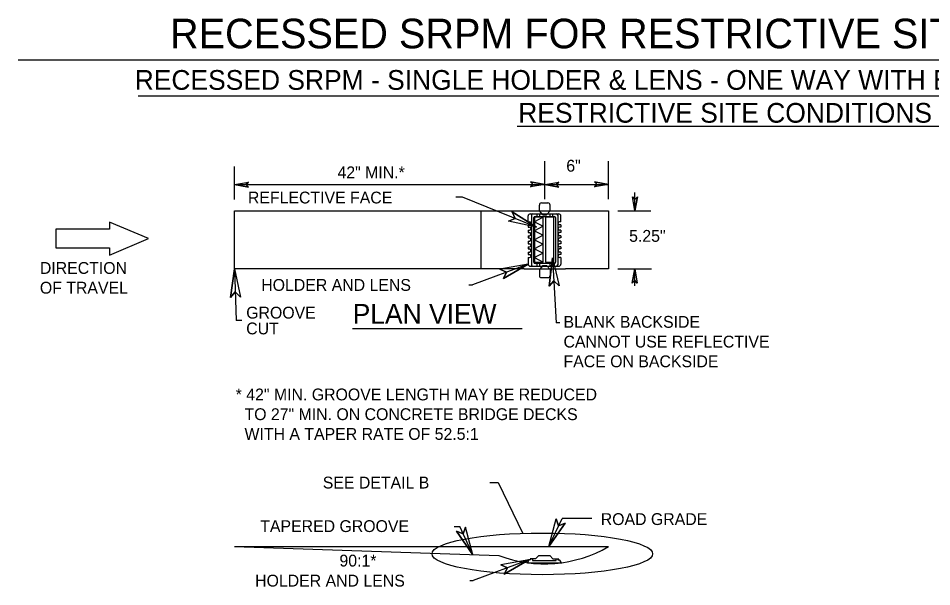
# Model space of a CAD drawing. Extents: x 12.2 to 19.6, y 5.9 to 16.3.
# Drawn here: x 12.247 to 16.872, y 13.404 to 16.284 of the extents above; entities that cross this region are included whole.
import ezdxf

# ---------------------------------------------------------------- set-up
doc = ezdxf.new("R2010")
doc.units = 0
for name, color, linetype in [('C-TRAF-FLOW', 7, 'Continuous'), ('DETL-DIMS', 7, 'Continuous'), ('DETL-LINE', 7, 'Continuous'), ('DETL-NOTE', 7, 'Continuous'), ('DETL-TITL', 7, 'Continuous')]:
    doc.layers.add(name, color=color, linetype=linetype)

msp = doc.modelspace()

# ---------------------------------------------------------------- linework, layer by layer
at = {"layer": 'C-TRAF-FLOW'}
msp.add_lwpolyline([(12.9062, 15.1683), (12.7089, 15.2519), (12.7089, 15.2152), (12.4365, 15.2152), (12.4365, 15.1214), (12.7089, 15.1214), (12.7089, 15.0847)], close=True, dxfattribs=at)
at = {"layer": 'DETL-DIMS'}
for p, q in [((14.9122, 15.3677), (14.9122, 15.5608)), ((15.2357, 15.3677), (15.2357, 15.5608)), ((13.3409, 15.3665), (13.3409, 15.5335)), ((13.3409, 15.442), (13.4125, 15.4541)), ((13.3989, 15.4416), (13.4125, 15.4541)), ((14.9122, 15.442), (14.8408, 15.4551)), ((14.8408, 15.4551), (14.8542, 15.4424)), ((14.9122, 15.442), (14.9838, 15.4541)), ((14.9702, 15.4416), (14.9838, 15.4541)), ((15.2357, 15.442), (15.1643, 15.4551)), ((15.1643, 15.4551), (15.1777, 15.4424)), ((13.3409, 15.442), (13.4123, 15.4289)), ((13.3409, 15.442), (14.9122, 15.442)), ((13.4123, 15.4289), (13.3989, 15.4416)), ((14.8542, 15.4424), (14.8406, 15.4299)), ((14.9122, 15.442), (14.8406, 15.4299)), ((14.9122, 15.442), (14.9836, 15.4289)), ((14.9122, 15.442), (15.2357, 15.442)), ((14.9836, 15.4289), (14.9702, 15.4416)), ((15.1777, 15.4424), (15.1641, 15.4299)), ((15.2357, 15.442), (15.1641, 15.4299)), ((14.4965, 15.3784), (14.4614, 15.3784)), ((14.8707, 15.2262), (14.4965, 15.3784)), ((15.3687, 15.3082), (15.3566, 15.3798)), ((15.3691, 15.3662), (15.3566, 15.3798)), ((15.3687, 15.3082), (15.3687, 15.4014)), ((15.3687, 15.3082), (15.3818, 15.3796)), ((15.3818, 15.3796), (15.3691, 15.3662)), ((14.7632, 15.27), (14.7288, 15.2568)), ((14.8707, 15.2262), (14.7478, 15.3034)), ((14.7478, 15.3034), (14.7632, 15.27)), ((15.2828, 15.3082), (15.4498, 15.3082)), ((14.8707, 15.2262), (14.7288, 15.2568)), ((14.8283, 15.0385), (14.5462, 14.9342)), ((14.8283, 15.0385), (14.6854, 15.0125)), ((14.8283, 15.0385), (14.7029, 14.9653)), ((14.9508, 15.0705), (14.9343, 14.9262)), ((14.9508, 15.0705), (14.9846, 14.9292)), ((14.9508, 15.0705), (14.9707, 14.741)), ((13.3409, 15.014), (13.3209, 14.8703)), ((13.3409, 15.014), (13.3503, 14.7528)), ((13.3409, 15.014), (13.3712, 14.872)), ((14.7195, 14.9983), (14.6854, 15.0125)), ((14.7029, 14.9653), (14.7195, 14.9983)), ((15.2828, 15.014), (15.4532, 15.014)), ((15.3687, 15.014), (15.3556, 14.9426)), ((15.3687, 15.014), (15.3808, 14.9424)), ((15.3687, 14.928), (15.3687, 15.014)), ((14.9343, 14.9262), (14.9578, 14.9546)), ((14.9578, 14.9546), (14.9846, 14.9292)), ((15.3556, 14.9426), (15.3683, 14.956)), ((15.3683, 14.956), (15.3808, 14.9424)), ((13.3209, 14.8703), (13.345, 14.8981)), ((13.345, 14.8981), (13.3712, 14.872)), ((14.5287, 14.9342), (14.5462, 14.9342)), ((13.3787, 14.7528), (13.3503, 14.7528)), ((14.9883, 14.741), (14.9707, 14.741)), ((14.9334, 13.6074), (14.9999, 13.7506)), ((14.9334, 13.6074), (14.9708, 13.7477)), ((14.9823, 13.7127), (14.9708, 13.7477)), ((15.1507, 13.7506), (14.9999, 13.7506)), ((14.4537, 13.7095), (14.4821, 13.7095)), ((14.5486, 13.5663), (14.4821, 13.7095)), ((14.4997, 13.6715), (14.5112, 13.7066)), ((14.5486, 13.5663), (14.5112, 13.7066)), ((14.9334, 13.6074), (15.0165, 13.7265)), ((15.0165, 13.7265), (14.9823, 13.7127)), ((14.5486, 13.5663), (14.4655, 13.6853)), ((14.4655, 13.6853), (14.4997, 13.6715)), ((14.8321, 13.5405), (14.55, 13.4362)), ((14.8321, 13.5405), (14.6892, 13.5145)), ((14.7232, 13.5003), (14.6892, 13.5145)), ((14.8321, 13.5405), (14.7067, 13.4673)), ((14.7067, 13.4673), (14.7232, 13.5003)), ((14.5325, 13.4362), (14.55, 13.4362))]:
    msp.add_line(p, q, dxfattribs=at)
for points in [[(13.4123, 15.4289), (13.3409, 15.442), (13.4125, 15.4541), (13.3989, 15.4416)], [(14.8408, 15.4551), (14.9122, 15.442), (14.8406, 15.4299), (14.8542, 15.4424)], [(14.9836, 15.4289), (14.9122, 15.442), (14.9838, 15.4541), (14.9702, 15.4416)], [(15.1643, 15.4551), (15.2357, 15.442), (15.1641, 15.4299), (15.1777, 15.4424)], [(15.3818, 15.3796), (15.3687, 15.3082), (15.3566, 15.3798), (15.3691, 15.3662)], [(14.7478, 15.3034), (14.8707, 15.2262), (14.7288, 15.2568), (14.7632, 15.27)], [(14.7029, 14.9653), (14.8283, 15.0385), (14.6854, 15.0125), (14.7195, 14.9983)], [(14.9343, 14.9262), (14.9508, 15.0705), (14.9846, 14.9292), (14.9578, 14.9546)], [(13.3209, 14.8703), (13.3409, 15.014), (13.3712, 14.872), (13.345, 14.8981)], [(15.3556, 14.9426), (15.3687, 15.014), (15.3808, 14.9424), (15.3683, 14.956)], [(15.0165, 13.7265), (14.9334, 13.6074), (14.9708, 13.7477), (14.9823, 13.7127)], [(14.4655, 13.6853), (14.5486, 13.5663), (14.5112, 13.7066), (14.4997, 13.6715)], [(14.7067, 13.4673), (14.8321, 13.5405), (14.6892, 13.5145), (14.7232, 13.5003)]]:
    msp.add_lwpolyline(points, close=True, dxfattribs=at)
msp.add_lwpolyline([(14.6351, 13.9324), (14.6771, 13.9324), (14.8009, 13.6747)], dxfattribs=at)
at = {"layer": 'DETL-LINE'}
for p, q in [((12.2466, 16.0733), (19.6208, 16.0733)), ((14.8851, 15.3078), (14.8851, 15.3379)), ((14.8957, 15.3485), (14.9288, 15.3485)), ((14.9394, 15.3078), (14.9394, 15.3379)), ((14.5888, 15.3082), (14.5888, 15.0141)), ((14.8089, 15.3082), (14.8851, 15.3082)), ((14.8283, 15.2526), (14.8283, 15.2825)), ((14.839, 15.2931), (14.9836, 15.2931)), ((14.8445, 15.2868), (14.8445, 15.0342)), ((14.8613, 15.2758), (14.8613, 15.0486)), ((14.9041, 15.2758), (14.8613, 15.2758)), ((14.9041, 15.2758), (14.8613, 15.2531)), ((14.8725, 15.2931), (14.8725, 15.2806)), ((14.8847, 15.3082), (14.9394, 15.3082)), ((14.9024, 15.2876), (14.8851, 15.3078)), ((14.8864, 15.2931), (14.8864, 15.2806)), ((14.9024, 15.2876), (14.9221, 15.2876)), ((14.9041, 15.0486), (14.9041, 15.2758)), ((14.9162, 15.2758), (14.9162, 15.0486)), ((14.9589, 15.2758), (14.9162, 15.2758)), ((14.9221, 15.2876), (14.9394, 15.3078)), ((14.9383, 15.2931), (14.9383, 15.2806)), ((14.9394, 15.3082), (15.0182, 15.3082)), ((14.9521, 15.2931), (14.9521, 15.2806)), ((14.9589, 15.0486), (14.9589, 15.2758)), ((14.978, 15.2868), (14.978, 15.0342)), ((14.9942, 15.2526), (14.9942, 15.2825)), ((14.8283, 15.2526), (14.8354, 15.2526)), ((14.8283, 15.2369), (14.8283, 15.2256)), ((14.8283, 15.2369), (14.8354, 15.2369)), ((14.8283, 15.2256), (14.8354, 15.2256)), ((14.8613, 15.2531), (14.9041, 15.2303)), ((14.9041, 15.2303), (14.8613, 15.2076)), ((14.9942, 15.2526), (14.9871, 15.2526)), ((14.9942, 15.2369), (14.9871, 15.2369)), ((14.9942, 15.2256), (14.9871, 15.2256)), ((14.9942, 15.2369), (14.9942, 15.2256)), ((14.8283, 15.2099), (14.8283, 15.1981)), ((14.8283, 15.2099), (14.8354, 15.2099)), ((14.8283, 15.1981), (14.8354, 15.1981)), ((14.8283, 15.1824), (14.8283, 15.1709)), ((14.8283, 15.1824), (14.8354, 15.1824)), ((14.8283, 15.1709), (14.8354, 15.1709)), ((14.8613, 15.2076), (14.9041, 15.1849)), ((14.9041, 15.1849), (14.8613, 15.1622)), ((14.9942, 15.2099), (14.9871, 15.2099)), ((14.9942, 15.1981), (14.9871, 15.1981)), ((14.9942, 15.1824), (14.9871, 15.1824)), ((14.9942, 15.1709), (14.9871, 15.1709)), ((14.9942, 15.2099), (14.9942, 15.1981)), ((14.9942, 15.1824), (14.9942, 15.1709)), ((14.8283, 15.1552), (14.8283, 15.1421)), ((14.8283, 15.1552), (14.8354, 15.1552)), ((14.8283, 15.1421), (14.8354, 15.1421)), ((14.8283, 15.1264), (14.8283, 15.1155)), ((14.8283, 15.1264), (14.8354, 15.1264)), ((14.8613, 15.1622), (14.9041, 15.1395)), ((14.9041, 15.1395), (14.8613, 15.1167)), ((14.9942, 15.1552), (14.9871, 15.1552)), ((14.9942, 15.1421), (14.9871, 15.1421)), ((14.9942, 15.1264), (14.9871, 15.1264)), ((14.9942, 15.1552), (14.9942, 15.1421)), ((14.9942, 15.1264), (14.9942, 15.1155)), ((14.8283, 15.1155), (14.8354, 15.1155)), ((14.8283, 15.0998), (14.8283, 15.0878)), ((14.8283, 15.0998), (14.8354, 15.0998)), ((14.8283, 15.0878), (14.8354, 15.0878)), ((14.8613, 15.1167), (14.9041, 15.094)), ((14.9041, 15.094), (14.8613, 15.0713)), ((14.9942, 15.1155), (14.9871, 15.1155)), ((14.9942, 15.0998), (14.9871, 15.0998)), ((14.9942, 15.0878), (14.9871, 15.0878)), ((14.9942, 15.0998), (14.9942, 15.0878)), ((14.8283, 15.0721), (14.8354, 15.0721)), ((14.8283, 15.0717), (14.8283, 15.0385)), ((14.8613, 15.0713), (14.9041, 15.0486)), ((14.8613, 15.0486), (14.9041, 15.0486)), ((14.8725, 15.042), (14.8725, 15.0278)), ((14.8864, 15.042), (14.8864, 15.0278)), ((14.9162, 15.0486), (14.9589, 15.0486)), ((14.9383, 15.042), (14.9383, 15.0278)), ((14.9521, 15.042), (14.9521, 15.0278)), ((14.9942, 15.0721), (14.9871, 15.0721)), ((14.9942, 15.0717), (14.9942, 15.0385)), ((14.8089, 15.0141), (14.8879, 15.0141)), ((14.839, 15.0278), (14.9836, 15.0278)), ((14.9024, 15.031), (14.8851, 15.0108)), ((14.8851, 15.0108), (14.8851, 14.9807)), ((14.8879, 15.0141), (14.9366, 15.0141)), ((14.9024, 15.031), (14.9221, 15.031)), ((14.9221, 15.031), (14.9394, 15.0108)), ((14.9366, 15.0141), (15.0182, 15.0141)), ((14.9394, 15.0108), (14.9394, 14.9807)), ((14.8957, 14.9701), (14.9288, 14.9701)), ((13.3409, 13.6074), (14.6806, 13.5618)), ((13.3409, 13.6074), (15.2357, 13.6074)), ((14.8679, 13.5466), (14.8829, 13.5621)), ((14.8829, 13.5621), (14.9385, 13.5621)), ((14.9385, 13.5621), (14.9534, 13.5456)), ((14.8321, 13.5405), (14.8243, 13.5254)), ((14.8243, 13.5254), (14.9972, 13.5254)), ((14.8398, 13.5405), (14.8321, 13.5405)), ((14.8381, 13.5466), (14.8679, 13.5466)), ((14.8398, 13.5466), (14.8398, 13.5405)), ((14.8509, 13.5466), (14.8509, 13.5369)), ((14.8509, 13.5369), (14.9704, 13.5369)), ((14.9534, 13.5456), (14.9836, 13.5456)), ((14.9704, 13.5369), (14.9704, 13.5456)), ((14.98, 13.5386), (14.98, 13.5456)), ((14.9889, 13.5386), (14.98, 13.5386)), ((14.9972, 13.5254), (14.9889, 13.5386))]:
    msp.add_line(p, q, dxfattribs=at)
for points in [[(14.8089, 15.0141), (13.3409, 15.014), (13.3409, 15.3082), (14.8089, 15.3082)], [(14.8573, 15.0484), (14.8573, 15.2742)], [(14.8637, 15.2806), (14.961, 15.2806)], [(14.9674, 15.2742), (14.9674, 15.0484)], [(15.0182, 15.3082), (15.2357, 15.3082), (15.2357, 15.0141), (15.0182, 15.0141)], [(14.961, 15.042), (14.8637, 15.042)]]:
    msp.add_lwpolyline(points, dxfattribs=at)
for centre, radius, start, end in [((14.8957, 15.3379), 0.0106, 90, 180), ((14.9288, 15.3379), 0.0106, 0, 90), ((14.839, 15.2825), 0.0106, 90, 180), ((14.8509, 15.2868), 0.00638, 90, 180), ((14.8637, 15.2742), 0.00638, 90, 180), ((14.961, 15.2742), 0.00638, 0, 90), ((14.9716, 15.2868), 0.00638, 0, 90), ((14.9836, 15.2825), 0.0106, 0, 90), ((14.8354, 15.2448), 0.00785, 270, 90), ((14.8354, 15.2177), 0.00785, 270, 90), ((14.9871, 15.2448), 0.00785, 90, 270), ((14.9871, 15.2177), 0.00785, 90, 270), ((14.8354, 15.1903), 0.00785, 270, 90), ((14.8354, 15.163), 0.00785, 270, 90), ((14.9871, 15.1903), 0.00785, 90, 270), ((14.9871, 15.163), 0.00785, 90, 270), ((14.8354, 15.1342), 0.00785, 270, 90), ((14.9871, 15.1342), 0.00785, 90, 270), ((14.8354, 15.1076), 0.00785, 270, 90), ((14.8354, 15.0799), 0.00785, 270, 90), ((14.9871, 15.1076), 0.00785, 90, 270), ((14.9871, 15.0799), 0.00785, 90, 270), ((14.839, 15.0385), 0.0106, 180, 270), ((14.8509, 15.0342), 0.00638, 180, 270), ((14.8637, 15.0484), 0.00638, 180, 270), ((14.961, 15.0484), 0.00638, 270, 0), ((14.9716, 15.0342), 0.00638, 270, 0), ((14.9836, 15.0385), 0.0106, 270, 0), ((14.8957, 14.9807), 0.0106, 180, 270), ((14.9288, 14.9807), 0.0106, 270, 0), ((14.9099, 14.1712), 0.6511, 249.3809, 300.0213)]:
    msp.add_arc(centre, radius, start, end, dxfattribs=at)
msp.add_ellipse((14.9003, 13.5708), major_axis=(0.5585, 0), ratio=0.188991, dxfattribs=at)
at = {"layer": 'DETL-TITL'}
for p, q in [((12.8539, 15.8915), (19.0254, 15.8915)), ((14.7728, 15.7379), (17.105, 15.7379)), ((13.9395, 14.7132), (14.7977, 14.7132))]:
    msp.add_line(p, q, dxfattribs=at)

# ---------------------------------------------------------------- texts
at = {"layer": 'DETL-NOTE'}
for s, p in [('6"', (15.0215, 15.5069)), ('42" MIN.*', (13.863, 15.4733)), ('REFLECTIVE FACE', (13.4094, 15.3458)), ('5.25"', (15.3397, 15.1516)), ('DIRECTION ', (12.356, 14.9891)), ('OF TRAVEL', (12.356, 14.889)), ('HOLDER AND LENS', (13.4769, 14.9031)), ('GROOVE', (13.4007, 14.7627)), ('BLANK BACKSIDE', (15.0074, 14.7161)), ('CUT', (13.4007, 14.6827)), ('CANNOT USE REFLECTIVE ', (15.0074, 14.6161)), ('FACE ON BACKSIDE', (15.0074, 14.5161)), ('* 42" MIN. GROOVE LENGTH MAY BE REDUCED ', (13.3476, 14.3483)), ('  TO 27" MIN. ON CONCRETE BRIDGE DECKS', (13.3476, 14.2483)), ('  WITH A TAPER RATE OF 52.5:1', (13.3476, 14.1483)), ('SEE DETAIL B', (13.7884, 13.9019)), ('TAPERED GROOVE', (13.4718, 13.6813)), ('ROAD GRADE', (15.1959, 13.7169)), ('90:1*', (13.8729, 13.5066)), ('HOLDER AND LENS', (13.4459, 13.4051))]:
    msp.add_text(s, height=0.06, dxfattribs=at).set_placement(p)
at = {"layer": 'DETL-TITL'}
for s, height, p in [('RECESSED SRPM FOR RESTRICTIVE SITE CONDITIONS', 0.15, (13.0148, 16.1318)), ('RECESSED SRPM - SINGLE HOLDER & LENS - ONE WAY WITH BLANK BACKSIDE', 0.1, (12.8363, 15.9216)), ('RESTRICTIVE SITE CONDITIONS', 0.1, (14.7782, 15.7549)), ('PLAN VIEW', 0.1, (13.9399, 14.7368))]:
    msp.add_text(s, height=height, dxfattribs=at).set_placement(p)

doc.saveas('drawing.dxf')
